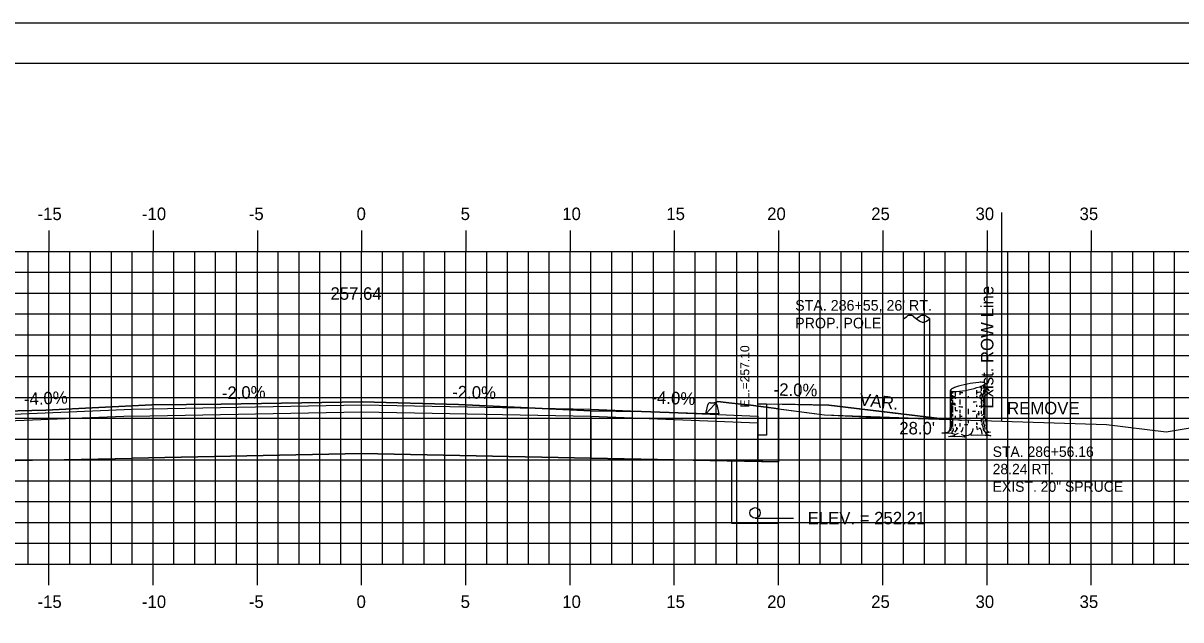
# Model space of a CAD drawing. Extents: x 856903 to 857073, y 366268 to 366378.
# Drawn here: x 856969.5 to 857025.1, y 366349.6 to 366378.2 of the extents above; entities that cross this region are included whole.
import ezdxf

# ---------------------------------------------------------------- set-up
doc = ezdxf.new("R2010")
doc.units = 0
for name, color, linetype in [('ANNOTATION', 7, 'Continuous'), ('BORDER', 7, 'Continuous'), ('D_Curb_Type_1_Rt', 7, 'Continuous'), ('D_Roadway_Centerline', 7, 'Continuous'), ('D_Roadway_Centerline_Text', 7, 'Continuous'), ('D_Roadway_Edge_Shoulder', 7, 'Continuous'), ('D_Roadway_FinishedGrade', 7, 'Continuous'), ('D_Roadway_SubGrade', 7, 'Continuous'), ('D_Text_Monospaced', 7, 'Continuous'), ('D_Text_Standard', 7, 'Continuous'), ('D_Utilities_Pole_Joint', 7, 'Continuous'), ('D_Utilities_Text', 7, 'Continuous'), ('E_ROW_Line', 7, 'Continuous'), ('H_V ANNOTATION', 7, 'Continuous'), ('JUNK COM EXC', 7, 'Continuous'), ('JUNK FILL', 7, 'Continuous'), ('junk strct exc', 7, 'Continuous'), ('MAJOR', 7, 'Continuous'), ('MINOR', 7, 'Continuous'), ('PDRAIN', 7, 'Continuous'), ('PLOT BOUNDARY', 7, 'Continuous'), ('S_Curb_Type_3', 7, 'Continuous'), ('S_Roadway_Centerline', 7, 'Continuous'), ('S_Trees_Conifer_Pay', 7, 'Continuous')]:
    doc.layers.add(name, color=color, linetype=linetype)

msp = doc.modelspace()

# ---------------------------------------------------------------- linework, layer by layer
at = {"layer": 'BORDER'}
msp.add_line((857070.784, 366376.236), (856910.784, 366376.236), dxfattribs=at)
at = {"layer": 'D_Curb_Type_1_Rt'}
msp.add_lwpolyline([(857005.201, 366359.924), (857005.201, 366358.424), (857004.784, 366358.424), (857004.784, 366359.924)], close=True, dxfattribs=at)
at = {"layer": 'D_Roadway_Centerline'}
msp.add_lwpolyline([(856974.784, 366359.661), (856985.784, 366359.881), (856996.784, 366359.661)], dxfattribs=at)
at = {"layer": 'D_Roadway_Edge_Shoulder'}
msp.add_line((857004.785, 366359.341), (857004.784, 366359.007), dxfattribs=at)
msp.add_lwpolyline([(856966.784, 366359.341), (856974.784, 366359.661), (856985.784, 366359.881), (856996.784, 366359.661), (857004.785, 366359.341)], dxfattribs=at)
at = {"layer": 'D_Roadway_FinishedGrade'}
for points in [[(857005.201, 366359.924), (857008.201, 366359.864)], [(857008.201, 366359.864), (857013.784, 366359.183)]]:
    msp.add_lwpolyline(points, dxfattribs=at)
at = {"layer": 'D_Roadway_SubGrade'}
msp.add_lwpolyline([(857005.784, 366359.913), (857005.784, 366357.147), (857004.784, 366357.167)], dxfattribs=at)
for points in [[(856974.784, 366359.327), (856966.784, 366359.007), (856966.784, 366357.167), (856974.784, 366357.327)], [(856974.784, 366357.327), (856974.784, 366359.327), (856985.784, 366359.547), (856996.784, 366359.327), (856996.784, 366357.327), (856985.784, 366357.547)], [(856996.784, 366359.327), (857004.784, 366359.007), (857004.784, 366357.167), (856996.784, 366357.327)]]:
    msp.add_lwpolyline(points, close=True, dxfattribs=at)
at = {"layer": 'D_Text_Standard'}
msp.add_lwpolyline([(857004.659, 366354.446), (857005.821, 366354.446), (857006.501, 366354.446)], dxfattribs=at)
at = {"layer": 'D_Utilities_Pole_Joint'}
for p, q in [((857011.784, 366364.005), (857011.94, 366364.115)), ((857011.784, 366359.247), (857011.784, 366364.005)), ((857012.252, 366364.115), (857012.409, 366364.005)), ((857012.565, 366364.115), (857012.409, 366364.005)), ((857012.409, 366364.005), (857012.565, 366363.894)), ((857013.034, 366364.005), (857012.878, 366364.115)), ((857012.878, 366363.894), (857013.034, 366364.005)), ((857013.034, 366359.247), (857013.034, 366364.005))]:
    msp.add_line(p, q, dxfattribs=at)
for centre, start, end in [((857012.096, 366363.894), 90, 125.2644), ((857012.096, 366363.894), 54.7356, 90), ((857012.721, 366363.894), 90, 125.2644), ((857012.721, 366363.894), 54.7356, 90), ((857012.721, 366364.115), 234.7356, 270), ((857012.721, 366364.115), 270, 305.2644)]:
    msp.add_arc(centre, 0.271, start, end, dxfattribs=at)
at = {"layer": 'E_ROW_Line'}
msp.add_line((857016.491, 366359.096), (857016.491, 366369.096), dxfattribs=at)
at = {"layer": 'JUNK COM EXC'}
for points in [[(856965.784, 366357.147), (856974.784, 366357.327), (856985.784, 366357.547), (856996.784, 366357.327), (857005.784, 366357.147), (857005.784, 366359.685)], [(857005.784, 366359.685), (857004.447, 366359.863), (857003.549, 366359.959), (857002.85, 366360.035), (857002.712, 366359.895), (857002.296, 366359.438), (856999.213, 366359.549), (856996.778, 366359.594), (856990.425, 366359.892), (856985.813, 366360.02), (856979.041, 366359.911), (856975.724, 366359.876), (856970.642, 366359.617), (856967.936, 366359.549)]]:
    msp.add_lwpolyline(points, dxfattribs=at)
at = {"layer": 'JUNK FILL'}
msp.add_lwpolyline([(857005.784, 366359.913), (857005.784, 366359.685), (857007.994, 366359.391), (857013.784, 366359.183), (857010.992, 366359.524), (857008.201, 366359.864)], close=True, dxfattribs=at)
at = {"layer": 'junk strct exc'}
msp.add_lwpolyline([(857003.534, 366357.192), (857003.534, 366354.196), (857005.784, 366354.196), (857005.784, 366357.147)], close=True, dxfattribs=at)
at = {"layer": 'MAJOR'}
for p, q in [((856970.784, 366368.238), (856970.784, 366367.236)), ((856975.784, 366368.238), (856975.784, 366367.236)), ((856980.784, 366368.238), (856980.784, 366367.236)), ((856985.784, 366368.238), (856985.784, 366367.236)), ((856990.784, 366368.238), (856990.784, 366367.236)), ((856995.784, 366368.238), (856995.784, 366367.236)), ((857000.784, 366368.238), (857000.784, 366367.236)), ((857005.784, 366368.238), (857005.784, 366367.236)), ((857010.784, 366368.238), (857010.784, 366367.236)), ((857015.784, 366368.238), (857015.784, 366367.236)), ((857020.784, 366368.238), (857020.784, 366367.236)), ((856915.784, 366367.236), (857055.784, 366367.236)), ((856915.784, 366367.236), (857055.784, 366367.236)), ((856970.784, 366352.236), (856970.784, 366367.236)), ((856975.784, 366352.236), (856975.784, 366367.236)), ((856980.784, 366352.236), (856980.784, 366367.236)), ((856985.784, 366352.236), (856985.784, 366367.236)), ((856990.784, 366352.236), (856990.784, 366367.236)), ((856995.784, 366352.236), (856995.784, 366367.236)), ((857000.784, 366352.236), (857000.784, 366367.236)), ((857005.784, 366352.236), (857005.784, 366367.236)), ((857010.784, 366352.236), (857010.784, 366367.236)), ((857015.784, 366352.236), (857015.784, 366367.236)), ((857020.784, 366352.236), (857020.784, 366367.236)), ((856915.784, 366362.236), (857055.784, 366362.236)), ((856915.784, 366357.236), (857055.784, 366357.236)), ((856915.784, 366352.236), (857055.784, 366352.236)), ((856915.784, 366352.236), (857055.784, 366352.236)), ((856970.784, 366351.234), (856970.784, 366352.236)), ((856975.784, 366351.234), (856975.784, 366352.236)), ((856980.784, 366351.234), (856980.784, 366352.236)), ((856985.784, 366351.234), (856985.784, 366352.236)), ((856990.784, 366351.234), (856990.784, 366352.236)), ((856995.784, 366351.234), (856995.784, 366352.236)), ((857000.784, 366351.234), (857000.784, 366352.236)), ((857005.784, 366351.234), (857005.784, 366352.236)), ((857010.784, 366351.234), (857010.784, 366352.236)), ((857015.784, 366351.234), (857015.784, 366352.236)), ((857020.784, 366351.234), (857020.784, 366352.236))]:
    msp.add_line(p, q, dxfattribs=at)
at = {"layer": 'MINOR'}
for p, q in [((856969.784, 366352.236), (856969.784, 366367.236)), ((856971.784, 366352.236), (856971.784, 366367.236)), ((856972.784, 366352.236), (856972.784, 366367.236)), ((856973.784, 366352.236), (856973.784, 366367.236)), ((856974.784, 366352.236), (856974.784, 366367.236)), ((856976.784, 366352.236), (856976.784, 366367.236)), ((856977.784, 366352.236), (856977.784, 366367.236)), ((856978.784, 366352.236), (856978.784, 366367.236)), ((856979.784, 366352.236), (856979.784, 366367.236)), ((856981.784, 366352.236), (856981.784, 366367.236)), ((856982.784, 366352.236), (856982.784, 366367.236)), ((856983.784, 366352.236), (856983.784, 366367.236)), ((856984.784, 366352.236), (856984.784, 366367.236)), ((856986.784, 366352.236), (856986.784, 366367.236)), ((856987.784, 366352.236), (856987.784, 366367.236)), ((856988.784, 366352.236), (856988.784, 366367.236)), ((856989.784, 366352.236), (856989.784, 366367.236)), ((856991.784, 366352.236), (856991.784, 366367.236)), ((856992.784, 366352.236), (856992.784, 366367.236)), ((856993.784, 366352.236), (856993.784, 366367.236)), ((856994.784, 366352.236), (856994.784, 366367.236)), ((856996.784, 366352.236), (856996.784, 366367.236)), ((856997.784, 366352.236), (856997.784, 366367.236)), ((856998.784, 366352.236), (856998.784, 366367.236)), ((856999.784, 366352.236), (856999.784, 366367.236)), ((857001.784, 366352.236), (857001.784, 366367.236)), ((857002.784, 366352.236), (857002.784, 366367.236)), ((857003.784, 366352.236), (857003.784, 366367.236)), ((857004.784, 366352.236), (857004.784, 366367.236)), ((857006.784, 366352.236), (857006.784, 366367.236)), ((857007.784, 366352.236), (857007.784, 366367.236)), ((857008.784, 366352.236), (857008.784, 366367.236)), ((857009.784, 366352.236), (857009.784, 366367.236)), ((857011.784, 366352.236), (857011.784, 366367.236)), ((857012.784, 366352.236), (857012.784, 366367.236)), ((857013.784, 366352.236), (857013.784, 366367.236)), ((857014.784, 366352.236), (857014.784, 366367.236)), ((857016.784, 366352.236), (857016.784, 366367.236)), ((857017.784, 366352.236), (857017.784, 366367.236)), ((857018.784, 366352.236), (857018.784, 366367.236)), ((857019.784, 366352.236), (857019.784, 366367.236)), ((857021.784, 366352.236), (857021.784, 366367.236)), ((857022.784, 366352.236), (857022.784, 366367.236)), ((857023.784, 366352.236), (857023.784, 366367.236)), ((857024.784, 366352.236), (857024.784, 366367.236)), ((856915.784, 366366.236), (857055.784, 366366.236)), ((856915.784, 366365.236), (857055.784, 366365.236)), ((856915.784, 366364.236), (857055.784, 366364.236)), ((856915.784, 366363.236), (857055.784, 366363.236)), ((856915.784, 366361.236), (857055.784, 366361.236)), ((856915.784, 366360.236), (857055.784, 366360.236)), ((856915.784, 366359.236), (857055.784, 366359.236)), ((856915.784, 366358.236), (857055.784, 366358.236)), ((856915.784, 366356.236), (857055.784, 366356.236)), ((856915.784, 366355.236), (857055.784, 366355.236)), ((856915.784, 366354.236), (857055.784, 366354.236)), ((856915.784, 366353.236), (857055.784, 366353.236))]:
    msp.add_line(p, q, dxfattribs=at)
at = {"layer": 'PDRAIN'}
msp.add_lwpolyline([(857003.534, 366357.192), (857003.534, 366354.196), (857005.784, 366354.196), (857005.784, 366357.147)], dxfattribs=at)
msp.add_circle((857004.659, 366354.696), 0.25, dxfattribs=at)
at = {"layer": 'PLOT BOUNDARY'}
msp.add_lwpolyline([(856902.691, 366268.177), (857072.691, 366268.177), (857072.691, 366378.177), (856902.691, 366378.177)], close=True, dxfattribs=at)
at = {"layer": 'S_Curb_Type_3'}
for points in [[(857002.818, 366359.883), (857002.921, 366359.438), (857002.296, 366359.438), (857002.399, 366359.883)], [(857002.521, 366359.98), (857002.697, 366359.98)]]:
    msp.add_lwpolyline(points, dxfattribs=at)
for centre, start, end in [((857002.521, 366359.855), 90, 167.0054), ((857002.697, 366359.855), 12.9946, 90)]:
    msp.add_arc(centre, 0.125, start, end, dxfattribs=at)
at = {"layer": 'S_Roadway_Centerline'}
msp.add_lwpolyline([(856967.936, 366359.549), (856970.642, 366359.617), (856975.724, 366359.876), (856979.041, 366359.911), (856985.813, 366360.02), (856990.425, 366359.892), (856996.778, 366359.594), (856999.213, 366359.549), (857002.296, 366359.438), (857002.712, 366359.895), (857002.85, 366360.035), (857003.549, 366359.959), (857004.447, 366359.863), (857007.994, 366359.391), (857009.968, 366359.305), (857021.509, 366358.935), (857024.373, 366358.587), (857026.776, 366358.981), (857038.061, 366358.662), (857038.485, 366358.646)], dxfattribs=at)
at = {"layer": 'S_Trees_Conifer_Pay'}
for p, q in [((857015.5, 366360.768), (857015.5, 366360.545)), ((857015.617, 366360.829), (857015.617, 366360.666)), ((857015.689, 366359.254), (857015.689, 366360.901)), ((857014.025, 366358.844), (857014.025, 366360.566)), ((857014.072, 366360.528), (857014.072, 366360.057)), ((857014.131, 366360.517), (857014.131, 366360.419)), ((857014.131, 366360.345), (857014.131, 366360.141)), ((857014.256, 366360.509), (857014.256, 366360.277)), ((857014.256, 366360.236), (857014.256, 366360.162)), ((857014.476, 366360.53), (857014.476, 366360.362)), ((857014.476, 366360.125), (857014.476, 366359.888)), ((857014.881, 366360.298), (857014.881, 366360.203)), ((857015.272, 366360.572), (857015.272, 366360.372)), ((857015.272, 366360.314), (857015.272, 366360.226)), ((857015.5, 366360.456), (857015.5, 366360.409)), ((857015.557, 366360.273), (857015.506, 366360.213)), ((857015.617, 366360.599), (857015.617, 366360.471)), ((857015.617, 366360.284), (857015.617, 366359.948)), ((857014.072, 366359.993), (857014.072, 366359.685)), ((857014.072, 366359.637), (857014.072, 366359.145)), ((857014.131, 366360.083), (857014.131, 366359.884)), ((857014.131, 366359.837), (857014.131, 366359.501)), ((857014.256, 366359.759), (857014.256, 366359.62)), ((857014.476, 366359.643), (857014.476, 366359.491)), ((857014.881, 366359.685), (857014.881, 366359.61)), ((857014.881, 366359.585), (857014.881, 366359.437)), ((857015.272, 366359.878), (857015.272, 366359.773)), ((857015.5, 366360.074), (857015.5, 366359.942)), ((857015.5, 366359.831), (857015.5, 366359.721)), ((857015.5, 366359.585), (857015.5, 366359.444)), ((857015.617, 366359.911), (857015.617, 366359.748)), ((857015.617, 366359.701), (857015.617, 366359.484)), ((857014.072, 366359.091), (857014.072, 366358.844)), ((857014.131, 366359.448), (857014.131, 366359.312)), ((857014.131, 366359.213), (857014.131, 366358.834)), ((857014.256, 366359.349), (857014.256, 366359.207)), ((857014.476, 366359.448), (857014.476, 366359.274)), ((857014.476, 366358.997), (857014.476, 366358.844)), ((857014.881, 366359.145), (857014.881, 366358.992)), ((857015.272, 366359.406), (857015.272, 366359.26)), ((857015.272, 366359.028), (857015.272, 366358.939)), ((857015.5, 366359.217), (857015.5, 366359.044)), ((857015.617, 366359.454), (857015.617, 366359.379)), ((857015.617, 366359.339), (857015.617, 366359.166)), ((857014.256, 366358.945), (857014.256, 366358.851)), ((857014.256, 366358.451), (857014.419, 366358.515)), ((857014.693, 366358.387), (857014.567, 366358.451))]:
    msp.add_line(p, q, dxfattribs=at)
for points in [[(857015.506, 366360.399), (857015.543, 366360.325), (857015.59, 366360.382), (857015.648, 366360.45), (857015.74, 366360.644), (857015.804, 366360.691), (857015.835, 366360.698)], [(857015.472, 366360.362), (857015.442, 366360.277), (857015.438, 366360.209), (857015.469, 366360.146)], [(857015.52, 366360.146), (857015.557, 366360.273), (857015.621, 366360.389), (857015.652, 366360.456), (857015.72, 366360.603)], [(857015.735, 366360.632), (857015.81, 366360.64), (857015.883, 366360.541)], [(857014.204, 366359.872), (857014.198, 366359.967), (857014.241, 366359.944), (857014.241, 366359.849)], [(857015.343, 366359.473), (857015.356, 366359.396), (857015.403, 366359.406), (857015.39, 366359.573)], [(857015.689, 366359.254), (857015.74, 366358.992), (857015.757, 366358.719), (857015.814, 366358.593), (857015.95, 366358.563), (857015.72, 366358.525), (857015.72, 366358.525), (857015.726, 366358.478), (857015.973, 366358.383), (857015.699, 366358.4), (857015.343, 366358.42), (857015.022, 366358.41), (857015.028, 366358.492), (857014.88, 366358.41), (857014.693, 366358.387), (857014.717, 366358.319), (857014.449, 366358.362), (857014.229, 366358.335), (857013.936, 366358.353), (857014.225, 366358.41), (857014.256, 366358.451), (857014.093, 366358.509), (857013.856, 366358.519), (857013.616, 366358.519), (857013.957, 366358.577), (857013.999, 366358.657), (857014.025, 366358.844)], [(857015.615, 366359.112), (857015.621, 366358.966), (857015.668, 366358.898), (857015.678, 366358.698)], [(857014.073, 366358.797), (857014.052, 366358.719), (857014.032, 366358.624)], [(857014.151, 366358.776), (857014.157, 366358.661), (857014.104, 366358.572), (857014.093, 366358.509)], [(857014.314, 366358.803), (857014.314, 366358.671), (857014.225, 366358.572)], [(857014.54, 366358.563), (857014.608, 366358.657), (857014.635, 366358.797)], [(857015.028, 366358.492), (857015.102, 366358.634), (857015.112, 366358.735)], [(857015.279, 366358.861), (857015.289, 366358.735), (857015.364, 366358.692)], [(857015.557, 366358.472), (857015.543, 366358.61), (857015.469, 366358.739)], [(857015.516, 366358.966), (857015.59, 366358.861), (857015.595, 366358.688), (857015.72, 366358.525)]]:
    msp.add_lwpolyline(points, dxfattribs=at)
for centre, radius, start, end in [((857014.524, 366359.96), 0.802, 108.0594, 124.2194), ((857015.881, 366355.798), 5.179, 101.7194, 108.0594), ((857015.881, 366355.798), 5.179, 95.3794, 101.7194), ((857013.833, 366365.669), 5.179, 281.7194, 288.0594), ((857015.47, 366360.156), 0.802, 79.2194, 95.3794), ((857015.19, 366361.507), 0.802, 288.0594, 304.2194), ((857015.358, 366361.215), 0.571, 284.4317, 292.4132), ((857015.574, 366360.697), 0.251, 71.0501, 79.2194), ((857015.5, 366361.051), 0.251, 304.2194, 312.3887), ((857015.557, 366360.87), 0.172, 300, 311.2506), ((857015.628, 366360.857), 0.0817, 56.7194, 71.0501), ((857015.614, 366360.927), 0.0817, 312.3887, 326.7194), ((857015.63, 366360.787), 0.0624, 311.2506, 330), ((857015.644, 366360.881), 0.0527, 46.923, 56.7194), ((857015.659, 366360.897), 0.0314, 34.2194, 46.923), ((857015.638, 366360.911), 0.0527, 326.7194, 336.5158), ((857015.646, 366360.778), 0.0441, 330, 343.9485), ((857015.663, 366360.9), 0.0264, 23.4074, 34.2194), ((857015.666, 366360.901), 0.0226, 11.7194, 23.4074), ((857015.658, 366360.902), 0.0314, 336.5158, 349.2194), ((857015.656, 366360.775), 0.0334, 343.9485, 354.2151), ((857015.666, 366360.901), 0.0226, 0.0315, 11.7194), ((857015.663, 366360.901), 0.0264, 349.2194, 0.0315), ((857014.057, 366360.388), 0.0334, 163.9485, 180), ((857014.057, 366360.388), 0.0334, 180, 196.0515), ((857014.052, 366360.565), 0.0264, 169.2194, 180.0315), ((857014.048, 366360.565), 0.0226, 180.0315, 191.7194), ((857014.067, 366360.39), 0.0441, 196.0515, 210), ((857014.056, 366360.565), 0.0314, 156.5158, 169.2194), ((857014.048, 366360.565), 0.0226, 191.7194, 203.4074), ((857014.051, 366360.567), 0.0264, 203.4074, 214.2194), ((857014.076, 366360.556), 0.0527, 146.7194, 156.5158), ((857014.055, 366360.57), 0.0314, 214.2194, 226.923), ((857014.083, 366360.4), 0.0624, 210, 228.7494), ((857014.1, 366360.54), 0.0817, 132.3887, 146.7194), ((857014.07, 366360.585), 0.0527, 226.923, 236.7194), ((857014.086, 366360.61), 0.0817, 236.7194, 251.0501), ((857014.156, 366360.482), 0.172, 228.7494, 240), ((857014.214, 366360.415), 0.251, 124.2194, 132.3887), ((857014.141, 366360.769), 0.251, 251.0501, 259.2194), ((857014.355, 366360.827), 0.571, 240, 240.3367), ((857014.356, 366360.616), 0.571, 240, 247.0587), ((857014.244, 366361.311), 0.802, 259.2194, 275.3794), ((857014.355, 366360.827), 0.571, 246.8597, 257.9846), ((857013.833, 366365.669), 5.179, 275.3794, 281.7194), ((857014.857, 366364.578), 4.124, 264.6955, 266.7331), ((857014.856, 366364.345), 4.124, 268.0751, 270), ((857014.856, 366364.345), 4.124, 270, 270.3581), ((857014.856, 366364.345), 4.124, 275.7849, 277.0558), ((857014.857, 366364.578), 4.124, 276.238, 278.1032), ((857015.358, 366361.06), 0.571, 278.1032, 284.3667), ((857015.358, 366360.616), 0.571, 284.4493, 297.0429), ((857015.358, 366361.06), 0.571, 297.0237, 300), ((857015.557, 366360.715), 0.172, 300, 311.2506), ((857015.63, 366360.633), 0.0624, 311.2506, 330), ((857015.646, 366360.623), 0.0441, 330, 343.9485), ((857015.656, 366360.62), 0.0334, 343.9485, 354.2151), ((857015.656, 366360.176), 0.0334, 343.9485, 354.2151), ((857014.057, 366359.941), 0.0334, 163.9485, 180), ((857014.057, 366359.941), 0.0334, 180, 196.0515), ((857014.057, 366359.731), 0.0334, 163.9485, 180), ((857014.057, 366359.731), 0.0334, 180, 196.0515), ((857014.067, 366359.944), 0.0441, 196.0515, 210), ((857014.067, 366359.734), 0.0441, 196.0515, 210), ((857014.083, 366359.953), 0.0624, 210, 228.7494), ((857014.083, 366359.743), 0.0624, 210, 228.7494), ((857014.156, 366360.035), 0.172, 228.7494, 240), ((857014.156, 366359.825), 0.172, 228.7494, 240), ((857014.355, 366360.38), 0.571, 240, 240.3367), ((857014.355, 366360.17), 0.571, 240, 246.8597), ((857014.355, 366360.17), 0.571, 259.2707, 261.8968), ((857014.856, 366363.688), 4.124, 261.8968, 263.1474), ((857014.856, 366363.898), 4.124, 264.081, 266.6676), ((857014.856, 366363.688), 4.124, 270, 270.3581), ((857014.856, 366363.688), 4.124, 273.1493, 275.4569), ((857014.857, 366364.134), 4.124, 273.7052, 275.9504), ((857014.856, 366363.898), 4.124, 277.6125, 278.1032), ((857015.357, 366360.38), 0.571, 278.1032, 286.9296), ((857015.357, 366360.38), 0.571, 297.1896, 300), ((857015.357, 366360.17), 0.571, 297.1896, 300), ((857015.556, 366360.035), 0.172, 300, 311.2506), ((857015.556, 366359.825), 0.172, 300, 311.2506), ((857015.628, 366359.953), 0.0624, 311.2506, 330), ((857015.628, 366359.743), 0.0624, 311.2506, 330), ((857015.644, 366359.944), 0.0441, 330, 343.9485), ((857015.644, 366359.734), 0.0441, 330, 343.9485), ((857015.654, 366359.941), 0.0334, 343.9485, 354.2151), ((857015.654, 366359.731), 0.0334, 343.9485, 354.2151), ((857014.057, 366359.494), 0.0334, 163.9485, 180), ((857014.057, 366359.494), 0.0334, 180, 196.0515), ((857014.057, 366359.296), 0.0334, 163.9485, 180), ((857014.057, 366359.101), 0.0334, 163.9485, 180), ((857014.057, 366359.101), 0.0334, 180, 196.0515), ((857014.067, 366359.497), 0.0441, 196.0515, 210), ((857014.067, 366359.104), 0.0441, 196.0515, 210), ((857014.083, 366359.506), 0.0624, 210, 228.7494), ((857014.083, 366359.113), 0.0624, 210, 228.7494), ((857014.156, 366359.589), 0.172, 228.7494, 240), ((857014.156, 366359.195), 0.172, 228.7494, 240), ((857014.355, 366359.934), 0.571, 240, 246.8597), ((857014.344, 366359.742), 0.571, 241.2369, 248.0268), ((857014.355, 366359.54), 0.571, 240, 246.8597), ((857014.856, 366363.254), 4.124, 263.4991, 265.8397), ((857014.856, 366363.451), 4.124, 264.716, 266.3193), ((857015.357, 366359.934), 0.571, 285.3983, 297.1896), ((857015.357, 366359.54), 0.571, 288.5067, 297.2721), ((857015.357, 366359.736), 0.571, 289.2907, 300), ((857015.556, 366359.391), 0.172, 300, 311.2506), ((857015.628, 366359.308), 0.0624, 311.2506, 330), ((857015.644, 366359.299), 0.0441, 330, 343.9485), ((857015.654, 366359.296), 0.0334, 343.9485, 354.2151), ((857014.057, 366358.88), 0.0334, 163.9485, 180), ((857014.057, 366358.88), 0.0334, 180, 196.0515), ((857014.067, 366358.883), 0.0441, 196.0515, 210), ((857014.083, 366358.892), 0.0624, 210, 228.7494), ((857014.156, 366358.975), 0.172, 228.7494, 240), ((857014.355, 366359.32), 0.571, 240, 244.5314), ((857014.856, 366362.838), 4.124, 262.4438, 263.512), ((857014.856, 366363.058), 4.124, 267.8117, 270), ((857014.856, 366363.058), 4.124, 270, 270.1328), ((857014.856, 366363.058), 4.124, 275.7849, 276.7896), ((857014.856, 366362.838), 4.124, 277.3684, 278.1032), ((857015.357, 366359.32), 0.571, 278.1032, 281.637), ((857015.556, 366358.975), 0.172, 300, 311.2506), ((857015.628, 366358.892), 0.0624, 311.2506, 330), ((857015.644, 366358.883), 0.0441, 330, 343.9485), ((857015.654, 366358.88), 0.0334, 343.9485, 354.2151)]:
    msp.add_arc(centre, radius, start, end, dxfattribs=at)

# ---------------------------------------------------------------- texts
at = {"layer": 'ANNOTATION'}
for s, rotation, p in [('-2.0%', 1.1458, (856979.087, 366360.147)), ('-2.0%', 358.8542, (856990.127, 366360.194)), ('-2.0%', 358.8543, (857005.544, 366360.318)), ('-4.0%', 2.2906, (856969.6, 366359.854)), ('-4.0%', 357.7094, (856999.679, 366359.945)), ('VAR.', 353.2778, (857009.637, 366359.852))]:
    msp.add_text(s, height=0.6, rotation=rotation, dxfattribs=at).set_placement(p)
msp.add_text('REMOVE', height=0.6, dxfattribs=at).set_placement((857016.748, 366359.42))
at = {"layer": 'D_Roadway_Centerline_Text'}
msp.add_text('257.64', height=0.6, dxfattribs=at).set_placement((856984.291, 366364.913))
at = {"layer": 'D_Text_Monospaced'}
for s, height, p in [('STA. 286+56.16', 0.49998, (857016.055, 366357.38)), ('28.24 RT.', 0.5, (857016.055, 366356.546)), ('EXIST. 20" SPRUCE', 0.49998, (857016.055, 366355.706))]:
    msp.add_text(s, height=height, dxfattribs=at).set_placement(p)
at = {"layer": 'D_Text_Standard'}
msp.add_text(' EL.=257.10', height=0.4335, rotation=90, dxfattribs=at).set_placement((857004.382, 366359.586))
for s, p in [("28.0'", (857011.576, 366358.458)), ('ELEV. = 252.21', (857007.181, 366354.146))]:
    msp.add_text(s, height=0.6, dxfattribs=at).set_placement(p)
at = {"layer": 'D_Utilities_Text'}
for s, p in [("STA. 286+55, 26' RT.", (857006.583, 366364.391)), ('PROP. POLE', (857006.583, 366363.541))]:
    msp.add_text(s, height=0.51, dxfattribs=at).set_placement(p)
at = {"layer": 'E_ROW_Line'}
msp.add_text('Exist. ROW Line', height=0.6, rotation=90, dxfattribs=at).set_placement((857016.091, 366359.696))
at = {"layer": 'H_V ANNOTATION'}
for s, p in [('-15', (856970.241, 366368.736)), ('-10', (856975.249, 366368.736)), ('-5', (856980.375, 366368.736)), ('0', (856985.543, 366368.736)), ('5', (856990.535, 366368.736)), ('10', (856995.409, 366368.736)), ('15', (857000.401, 366368.736)), ('20', (857005.238, 366368.736)), ('25', (857010.23, 366368.736)), ('30', (857015.233, 366368.736)), ('35', (857020.225, 366368.736)), ('-15', (856970.241, 366350.136)), ('-10', (856975.249, 366350.136)), ('-5', (856980.375, 366350.136)), ('0', (856985.543, 366350.136)), ('5', (856990.535, 366350.136)), ('10', (856995.409, 366350.136)), ('15', (857000.401, 366350.136)), ('20', (857005.238, 366350.136)), ('25', (857010.23, 366350.136)), ('30', (857015.233, 366350.136)), ('35', (857020.225, 366350.136))]:
    msp.add_text(s, height=0.6, dxfattribs=at).set_placement(p)
at = {"layer": 'S_Roadway_Centerline'}
for s, p in [('C', (856985.808, 366360.02)), ('L', (856985.813, 366360.013))]:
    msp.add_text(s, height=0.0146, dxfattribs=at).set_placement(p)

doc.saveas('drawing.dxf')
